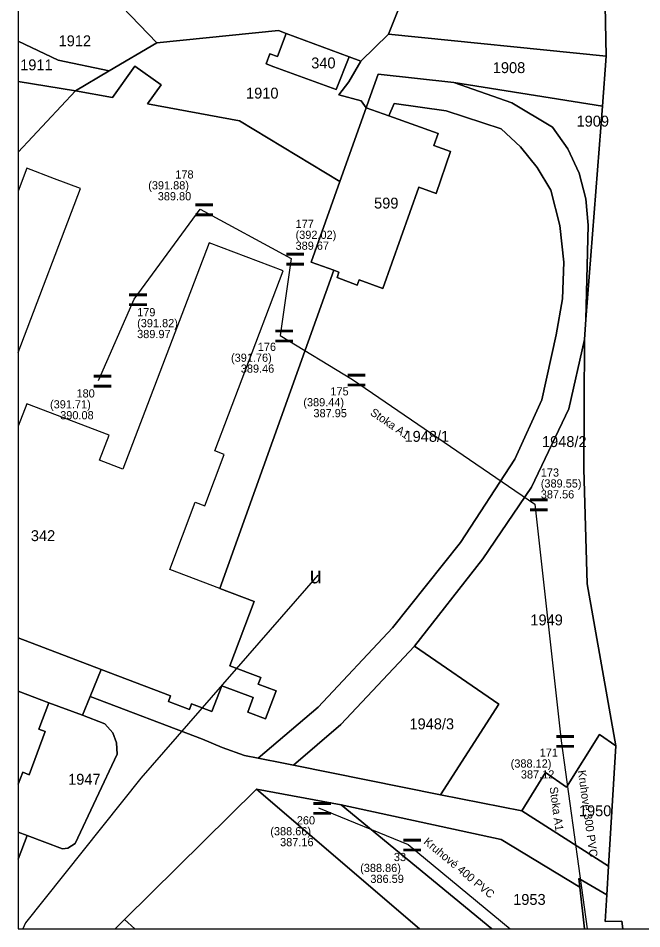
# Model space of a CAD drawing. Extents: x -564940 to -564406, y -1066466 to -1066072.
# Drawn here: x -564940.4 to -564826.1, y -1066465.6 to -1066298.6 of the extents above; entities that cross this region are included whole.
import ezdxf

# ---------------------------------------------------------------- set-up
doc = ezdxf.new("R2010")
doc.units = 0
for name, color, linetype in [('ft_g_5211', 7, 'Continuous'), ('ft_g_5916', 7, 'Continuous'), ('ft_g_6101', 7, 'Continuous'), ('ft_g_6101_ft_g_6101_da_6108_gtc_da_6108', 7, 'Continuous'), ('ft_g_stoka', 7, 'Continuous'), ('ft_g_stoka_ft_g_stoka_da_oznaceni_gtc_da_6027', 7, 'Continuous'), ('ft_g_stoka_ft_g_stoka_da_popis_gtc_da_6004', 7, 'Continuous'), ('ft_parcela_polygon', 7, 'Continuous'), ('ft_parcela_text', 7, 'Continuous'), ('ft_stavebni_objekt_polygon', 7, 'Continuous')]:
    doc.layers.add(name, color=color, linetype=linetype)

msp = doc.modelspace()

# ---------------------------------------------------------------- linework, layer by layer
at = {"layer": 'ft_g_5211'}
msp.add_lwpolyline([(-564885.49, -1066400.78), (-564917.93, -1066437.99), (-564939.11, -1066464.56), (-564939.59, -1066465.63)], dxfattribs=at)
at = {"layer": 'ft_g_stoka'}
for p, q in [((-564919.17, -1066350.17), (-564907.06, -1066333.68)), ((-564907.06, -1066333.68), (-564890.37, -1066342.73)), ((-564890.37, -1066342.73), (-564892.39, -1066356.81)), ((-564925.69, -1066365.1), (-564919.17, -1066350.17)), ((-564892.39, -1066356.81), (-564879.13, -1066364.89)), ((-564879.13, -1066364.89), (-564845.68, -1066387.78)), ((-564845.68, -1066387.78), (-564840.85, -1066431.16)), ((-564885.39, -1066443.44), (-564868.91, -1066450.17)), ((-564868.91, -1066450.17), (-564850.24, -1066465.63))]:
    msp.add_line(p, q, dxfattribs=at)
msp.add_lwpolyline([(-564840.85, -1066431.16), (-564836.12, -1066465.63)], dxfattribs=at)
at = {"layer": 'ft_parcela_polygon'}
for p, q in [((-564940.44, -1066293.32), (-564940.44, -1066302.85)), ((-564940.44, -1066302.85), (-564940.44, -1066310.27)), ((-564940.44, -1066310.27), (-564940.44, -1066323.19)), ((-564940.44, -1066323.19), (-564940.44, -1066412.3)), ((-564940.44, -1066412.3), (-564940.44, -1066422.07)), ((-564940.44, -1066422.07), (-564940.44, -1066439.12)), ((-564940.44, -1066439.12), (-564940.44, -1066447.89)), ((-564940.44, -1066447.89), (-564940.44, -1066452.89)), ((-564922.65, -1066465.63), (-564919.05, -1066465.63)), ((-564919.05, -1066465.63), (-564866.87, -1066465.63)), ((-564866.87, -1066465.63), (-564853.59, -1066465.63)), ((-564853.59, -1066465.63), (-564836.6, -1066465.63)), ((-564836.6, -1066465.63), (-564829.56, -1066465.63)), ((-564829.56, -1066465.63), (-564789.13, -1066465.63))]:
    msp.add_line(p, q, dxfattribs=at)
for points in [[(-564827.92, -1066185.94), (-564831.63, -1066222.49), (-564831.07, -1066257.56), (-564837.82, -1066261.45), (-564833.11, -1066280.79), (-564832.6, -1066305.6), (-564833.32, -1066314.79), (-564836.37, -1066353.9), (-564836.61, -1066357.54), (-564836.7, -1066381.26), (-564836.11, -1066402.4), (-564830.86, -1066432.08), (-564832.2, -1066454.17), (-564832.49, -1066459.38), (-564832.78, -1066464.3), (-564829.72, -1066464.22), (-564829.56, -1066465.63)], [(-564940.44, -1066293.32), (-564921.38, -1066296.58), (-564915.01, -1066303.13), (-564892.71, -1066300.89), (-564891.3, -1066301.42), (-564879.77, -1066305.7), (-564877.59, -1066306.51), (-564872.55, -1066301.58), (-564855.75, -1066259.5), (-564865.85, -1066270.7), (-564875.41, -1066280.59), (-564887.16, -1066289.39), (-564890.46, -1066280.92), (-564879.36, -1066263.45), (-564894.07, -1066255.56), (-564918.86, -1066268.33), (-564928.69, -1066268.58), (-564940.44, -1066282.41)], [(-564940.44, -1066302.85), (-564933.09, -1066306.36), (-564923.79, -1066308.32), (-564915.01, -1066303.13), (-564921.38, -1066296.58), (-564940.44, -1066293.32)], [(-564940.44, -1066310.27), (-564929.94, -1066311.95), (-564923.79, -1066308.32), (-564933.09, -1066306.36), (-564940.44, -1066302.85)], [(-564940.44, -1066412.3), (-564925.24, -1066418.08), (-564912.49, -1066422.92), (-564912.88, -1066423.94), (-564909.04, -1066425.4), (-564908.65, -1066424.38), (-564904.91, -1066425.8), (-564903.1, -1066421.05), (-564897.35, -1066423.23), (-564898.36, -1066425.89), (-564895.09, -1066427.13), (-564893.14, -1066421.99), (-564896.41, -1066420.75), (-564895.96, -1066419.56), (-564901.61, -1066417.41), (-564897.14, -1066405.63), (-564903.44, -1066403.23), (-564882.58, -1066344.86), (-564886.71, -1066343.39), (-564881.44, -1066328.57), (-564899.83, -1066317.48), (-564916.76, -1066314.37), (-564914.25, -1066310.85), (-564919.07, -1066307.42), (-564923.18, -1066313.19), (-564929.94, -1066311.95), (-564940.44, -1066323.19)], [(-564940.44, -1066323.19), (-564929.94, -1066311.95), (-564940.44, -1066310.27)], [(-564940.44, -1066422.07), (-564934.81, -1066424.19), (-564928.68, -1066426.48), (-564927.27, -1066423.03), (-564925.24, -1066418.08), (-564940.44, -1066412.3)], [(-564940.44, -1066439.12), (-564939.62, -1066436.94), (-564938.42, -1066437.38), (-564935.48, -1066429.44), (-564936.63, -1066429.01), (-564934.81, -1066424.19), (-564940.44, -1066422.07)], [(-564922.65, -1066465.63), (-564920.95, -1066463.95), (-564896.74, -1066440.02), (-564881.24, -1066442.9), (-564851.89, -1066449.23), (-564837.46, -1066457.99), (-564837.64, -1066456.4), (-564832.49, -1066459.38), (-564832.2, -1066454.17), (-564848.1, -1066444.03), (-564862.99, -1066441.05), (-564889.97, -1066435.64), (-564891.51, -1066435.33), (-564896.45, -1066434.35), (-564898.94, -1066433.85), (-564903.01, -1066432.38), (-564906.67, -1066430.85), (-564927.27, -1066423.03), (-564928.68, -1066426.48), (-564924.53, -1066428.02), (-564923.08, -1066429.7), (-564922.41, -1066431.54), (-564922.32, -1066433.63), (-564930.02, -1066449.98), (-564931.33, -1066450.87), (-564932.33, -1066450.98), (-564938.78, -1066448.52), (-564940.44, -1066452.89)], [(-564940.44, -1066447.89), (-564938.78, -1066448.52), (-564932.33, -1066450.98), (-564931.33, -1066450.87), (-564930.02, -1066449.98), (-564922.32, -1066433.63), (-564922.41, -1066431.54), (-564923.08, -1066429.7), (-564924.53, -1066428.02), (-564928.68, -1066426.48), (-564934.81, -1066424.19), (-564936.63, -1066429.01), (-564935.48, -1066429.44), (-564938.42, -1066437.38), (-564939.62, -1066436.94), (-564940.44, -1066439.12)], [(-564866.87, -1066465.63), (-564896.74, -1066440.02), (-564920.95, -1066463.95), (-564919.05, -1066465.63)], [(-564853.59, -1066465.63), (-564881.24, -1066442.9), (-564896.74, -1066440.02), (-564866.87, -1066465.63)], [(-564836.6, -1066465.63), (-564837.46, -1066457.99), (-564851.89, -1066449.23), (-564881.24, -1066442.9), (-564853.59, -1066465.63)], [(-564940.44, -1066452.89), (-564938.78, -1066448.52), (-564940.44, -1066447.89)], [(-564940.44, -1066452.89), (-564940.44, -1066465.63), (-564922.65, -1066465.63)], [(-564829.56, -1066465.63), (-564829.72, -1066464.22), (-564832.78, -1066464.3), (-564832.49, -1066459.38), (-564837.64, -1066456.4), (-564837.46, -1066457.99), (-564836.6, -1066465.63)], [(-564919.05, -1066465.63), (-564920.95, -1066463.95), (-564922.65, -1066465.63)]]:
    msp.add_lwpolyline(points, dxfattribs=at)
for points in [[(-564872.55, -1066301.58), (-564832.6, -1066305.6), (-564833.11, -1066280.79), (-564837.82, -1066261.45), (-564855.75, -1066259.5)], [(-564894.99, -1066307.03), (-564894.3, -1066305.16), (-564892.88, -1066305.68), (-564891.3, -1066301.42), (-564892.71, -1066300.89), (-564915.01, -1066303.13), (-564923.79, -1066308.32), (-564929.94, -1066311.95), (-564923.18, -1066313.19), (-564919.07, -1066307.42), (-564914.25, -1066310.85), (-564916.76, -1066314.37), (-564899.83, -1066317.48), (-564881.44, -1066328.57), (-564876.64, -1066315.07), (-564877.55, -1066313.8), (-564881.64, -1066312.69), (-564879.8, -1066310.29), (-564877.59, -1066306.51), (-564879.77, -1066305.7), (-564882.15, -1066311.73), (-564893.58, -1066307.55)], [(-564893.58, -1066307.55), (-564882.15, -1066311.73), (-564879.77, -1066305.7), (-564891.3, -1066301.42), (-564892.88, -1066305.68), (-564894.3, -1066305.16), (-564894.99, -1066307.03)], [(-564832.6, -1066305.6), (-564872.55, -1066301.58), (-564877.59, -1066306.51), (-564879.8, -1066310.29), (-564881.64, -1066312.69), (-564877.55, -1066313.8), (-564876.64, -1066315.07), (-564876.14, -1066313.65), (-564874.45, -1066308.9), (-564860.56, -1066310.41), (-564833.32, -1066314.79)], [(-564881.25, -1066428.16), (-564867.78, -1066413.78), (-564855.24, -1066397.79), (-564846.32, -1066384.63), (-564839.47, -1066370.29), (-564836.61, -1066357.54), (-564836.37, -1066353.9), (-564835.94, -1066336.62), (-564836.34, -1066331.75), (-564837.59, -1066327.03), (-564839.67, -1066322.61), (-564842.49, -1066318.62), (-564849.89, -1066314.15), (-564860.56, -1066310.41), (-564874.45, -1066308.9), (-564876.14, -1066313.65), (-564876.64, -1066315.07), (-564872.46, -1066316.56), (-564871.52, -1066314.29), (-564861.97, -1066315.6), (-564851.85, -1066318.93), (-564848.32, -1066322.25), (-564845.28, -1066326.01), (-564842.77, -1066330.15), (-564841.09, -1066336.67), (-564840.36, -1066343.37), (-564840.6, -1066350.09), (-564841.81, -1066356.72), (-564844.42, -1066368.64), (-564849.36, -1066379.52), (-564859.35, -1066394.77), (-564871.81, -1066410.45), (-564885.41, -1066425.02), (-564896.45, -1066434.35), (-564891.51, -1066435.33), (-564889.97, -1066435.64)], [(-564835.94, -1066336.62), (-564836.37, -1066353.9), (-564833.32, -1066314.79), (-564860.56, -1066310.41), (-564849.89, -1066314.15), (-564842.49, -1066318.62), (-564839.67, -1066322.61), (-564837.59, -1066327.03), (-564836.34, -1066331.75)], [(-564906.67, -1066430.85), (-564903.01, -1066432.38), (-564898.94, -1066433.85), (-564896.45, -1066434.35), (-564885.41, -1066425.02), (-564871.81, -1066410.45), (-564859.35, -1066394.77), (-564849.36, -1066379.52), (-564844.42, -1066368.64), (-564841.81, -1066356.72), (-564840.6, -1066350.09), (-564840.36, -1066343.37), (-564841.09, -1066336.67), (-564842.77, -1066330.15), (-564845.28, -1066326.01), (-564848.32, -1066322.25), (-564851.85, -1066318.93), (-564861.97, -1066315.6), (-564871.52, -1066314.29), (-564872.46, -1066316.56), (-564863.45, -1066319.76), (-564864.25, -1066322.01), (-564861.14, -1066323.11), (-564863.81, -1066330.76), (-564866.96, -1066329.64), (-564873.56, -1066348.2), (-564877.94, -1066346.64), (-564878.29, -1066347.63), (-564881.98, -1066346.2), (-564881.62, -1066345.2), (-564882.58, -1066344.86), (-564903.44, -1066403.23), (-564897.14, -1066405.63), (-564901.61, -1066417.41), (-564895.96, -1066419.56), (-564896.41, -1066420.75), (-564893.14, -1066421.99), (-564895.09, -1066427.13), (-564898.36, -1066425.89), (-564897.35, -1066423.23), (-564903.1, -1066421.05), (-564904.91, -1066425.8), (-564908.65, -1066424.38), (-564909.04, -1066425.4), (-564912.88, -1066423.94), (-564912.49, -1066422.92), (-564925.24, -1066418.08), (-564927.27, -1066423.03)], [(-564881.62, -1066345.2), (-564881.98, -1066346.2), (-564878.29, -1066347.63), (-564877.94, -1066346.64), (-564873.56, -1066348.2), (-564866.96, -1066329.64), (-564863.81, -1066330.76), (-564861.14, -1066323.11), (-564864.25, -1066322.01), (-564863.45, -1066319.76), (-564872.46, -1066316.56), (-564876.64, -1066315.07), (-564881.44, -1066328.57), (-564886.71, -1066343.39), (-564882.58, -1066344.86)], [(-564867.78, -1066413.78), (-564852.29, -1066424.43), (-564862.99, -1066441.05), (-564848.1, -1066444.03), (-564843.75, -1066436.98), (-564839.89, -1066439.69), (-564833.83, -1066430.02), (-564830.86, -1066432.08), (-564836.11, -1066402.4), (-564836.7, -1066381.26), (-564836.61, -1066357.54), (-564839.47, -1066370.29), (-564846.32, -1066384.63), (-564855.24, -1066397.79)], [(-564852.29, -1066424.43), (-564867.78, -1066413.78), (-564881.25, -1066428.16), (-564889.97, -1066435.64), (-564862.99, -1066441.05)], [(-564832.2, -1066454.17), (-564830.86, -1066432.08), (-564833.83, -1066430.02), (-564839.89, -1066439.69), (-564843.75, -1066436.98), (-564848.1, -1066444.03)]]:
    msp.add_lwpolyline(points, close=True, dxfattribs=at)
at = {"layer": 'ft_stavebni_objekt_polygon'}
for p, q in [((-564940.44, -1066330.35), (-564940.44, -1066359.93)), ((-564940.44, -1066373.46), (-564940.44, -1066412.3)), ((-564940.44, -1066422.07), (-564940.44, -1066439.12))]:
    msp.add_line(p, q, dxfattribs=at)
for points in [[(-564940.44, -1066359.93), (-564929.04, -1066329.9), (-564933.8, -1066328.09), (-564938.85, -1066326.17), (-564940.44, -1066330.35)], [(-564940.44, -1066412.3), (-564925.24, -1066418.08), (-564912.49, -1066422.92), (-564912.88, -1066423.94), (-564909.04, -1066425.4), (-564908.65, -1066424.38), (-564904.91, -1066425.8), (-564903.1, -1066421.05), (-564897.35, -1066423.23), (-564898.36, -1066425.89), (-564895.09, -1066427.13), (-564893.14, -1066421.99), (-564896.41, -1066420.75), (-564895.96, -1066419.56), (-564901.61, -1066417.41), (-564897.14, -1066405.63), (-564903.44, -1066403.23), (-564912.65, -1066399.73), (-564907.97, -1066387.4), (-564906.24, -1066388.05), (-564902.66, -1066378.63), (-564904.39, -1066377.97), (-564891.85, -1066344.97), (-564905.45, -1066339.81), (-564921.24, -1066381.36), (-564925.54, -1066379.72), (-564923.78, -1066375.1), (-564938.88, -1066369.36), (-564940.44, -1066373.46)], [(-564940.44, -1066439.12), (-564939.62, -1066436.94), (-564938.42, -1066437.38), (-564935.48, -1066429.44), (-564936.63, -1066429.01), (-564934.81, -1066424.19), (-564940.44, -1066422.07)]]:
    msp.add_lwpolyline(points, dxfattribs=at)

# ---------------------------------------------------------------- texts
at = {"layer": 'ft_g_5916'}
msp.add_text('u', height=3, dxfattribs=at).set_placement((-564886.99, -1066402.28))
at = {"layer": 'ft_g_6101'}
for p in [(-564908.31, -1066336.18), (-564891.62, -1066345.23), (-564920.42, -1066352.67), (-564893.64, -1066359.31), (-564880.38, -1066367.39), (-564926.94, -1066367.6), (-564846.93, -1066390.28), (-564842.1, -1066433.66), (-564886.64, -1066445.94), (-564870.16, -1066452.67)]:
    msp.add_text('=', height=5, dxfattribs=at).set_placement(p)
at = {"layer": 'ft_g_6101_ft_g_6101_da_6108_gtc_da_6108'}
for s, p in [('178', (-564911.63, -1066328.04)), ('(391.88)', (-564916.6, -1066330.04)), ('389.80', (-564914.85, -1066332.04)), ('177', (-564889.58, -1066337.11)), ('(392.02)', (-564889.58, -1066339.11)), ('389.67', (-564889.58, -1066341.11)), ('179', (-564918.63, -1066353.31)), ('(391.82)', (-564918.63, -1066355.31)), ('389.97', (-564918.63, -1066357.31)), ('176', (-564896.51, -1066359.65)), ('(391.76)', (-564901.42, -1066361.65)), ('389.46', (-564899.62, -1066363.65)), ('180', (-564929.75, -1066368.2)), ('175', (-564883.19, -1066367.82)), ('(391.71)', (-564934.61, -1066370.2)), ('(389.44)', (-564888.16, -1066369.82)), ('387.95', (-564886.3, -1066371.82)), ('390.08', (-564932.74, -1066372.2)), ('173', (-564844.61, -1066382.71)), ('(389.55)', (-564844.61, -1066384.71)), ('387.56', (-564844.61, -1066386.71)), ('171', (-564844.8, -1066434.07)), ('(388.12)', (-564850.13, -1066436.07)), ('387.12', (-564848.26, -1066438.07)), ('260', (-564889.35, -1066446.49)), ('(388.66)', (-564894.21, -1066448.49)), ('387.16', (-564892.41, -1066450.49)), ('33', (-564871.55, -1066453.22)), ('(388.86)', (-564877.73, -1066455.22)), ('386.59', (-564875.86, -1066457.22))]:
    msp.add_text(s, height=1.5, dxfattribs=at).set_placement(p)
at = {"layer": 'ft_g_stoka_ft_g_stoka_da_oznaceni_gtc_da_6027'}
for rotation, p in [(325.616, (-564876.03, -1066371.28)), (277.8118, (-564843.01, -1066439.69))]:
    msp.add_text('Stoka A1', height=1.5, rotation=rotation, dxfattribs=at).set_placement(p)
at = {"layer": 'ft_g_stoka_ft_g_stoka_da_popis_gtc_da_6004'}
for s, rotation, p in [('Kruhové 300 PVC', 277.8118, (-564837.82, -1066436.64)), ('Kruhové 400 PVC', 320.3643, (-564866.23, -1066449.9))]:
    msp.add_text(s, height=1.5, rotation=rotation, dxfattribs=at).set_placement(p)
at = {"layer": 'ft_parcela_text'}
for s, p in [('1912', (-564933.03, -1066303.79)), ('1911', (-564940.08, -1066308.2)), ('340', (-564886.71, -1066307.85)), ('1908', (-564853.41, -1066308.71)), ('1910', (-564898.66, -1066313.38)), ('1909', (-564838.05, -1066318.52)), ('599', (-564875.18, -1066333.55)), ('1948/1', (-564869.6, -1066376.33)), ('1948/2', (-564844.39, -1066377.29)), ('342', (-564938.12, -1066394.54)), ('1949', (-564846.52, -1066409.99)), ('1948/3', (-564868.69, -1066429.06)), ('1947', (-564931.29, -1066439.21)), ('1950', (-564837.62, -1066444.99)), ('1953', (-564849.67, -1066461.25))]:
    msp.add_text(s, height=2, dxfattribs=at).set_placement(p)

doc.saveas('drawing.dxf')
